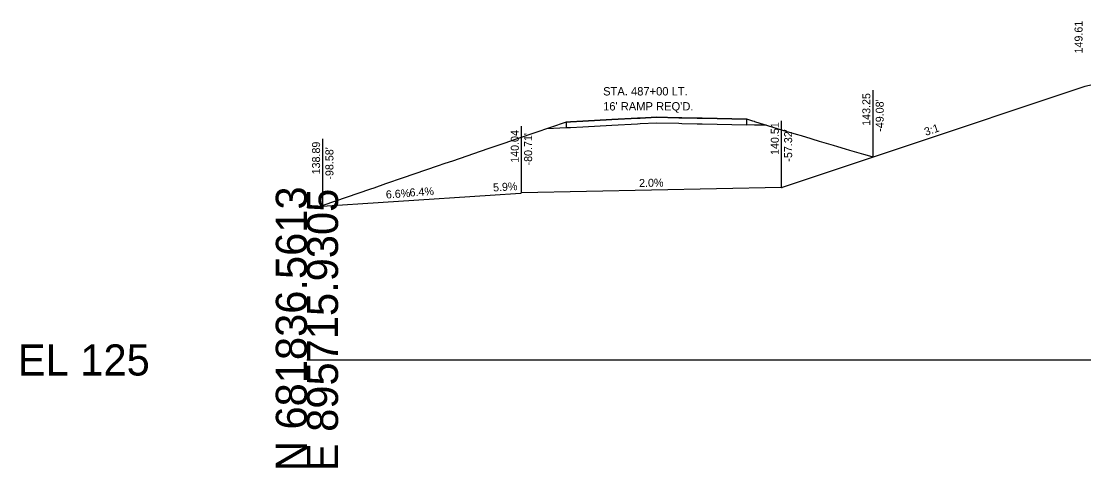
# Model space of a CAD drawing. Extents: x -26 to 4403, y -13 to 9578.
# Drawn here: x 2974.3 to 3069.9, y 8990.3 to 9030.5 of the extents above; entities that cross this region are included whole.
import ezdxf

# ---------------------------------------------------------------- set-up
doc = ezdxf.new("R2010")
doc.units = 0
for name, color, linetype in [('CONST_LV3', 7, 'Continuous'), ('Draft_XS_Grid', 7, 'Continuous'), ('DTM_CONTOURS_MINOR', 7, 'Continuous'), ('DTM_P_FINISHED_GRADE', 7, 'Continuous'), ('DTM_X_GROUND', 7, 'Continuous'), ('X_PROFILES_1', 7, 'Continuous'), ('XS_CELL', 7, 'Continuous'), ('XS_P_DR_GRAVEL', 7, 'Continuous'), ('XS_P_DRAINAGE', 7, 'Continuous'), ('XS_P_GROUND', 7, 'Continuous'), ('XS_P_TX_CLEARZONE', 7, 'Continuous'), ('XS_P_TX_FS_BS', 7, 'Continuous')]:
    doc.layers.add(name, color=color, linetype=linetype)

msp = doc.modelspace()

# ---------------------------------------------------------------- linework, layer by layer
at = {"layer": 'CONST_LV3'}
msp.add_lwpolyline([(3023.32, 9021.398), (3023.721, 9021.419), (3024.83, 9021.479), (3027.436, 9021.619), (3029.722, 9021.741), (3029.968, 9021.754), (3031.434, 9021.833), (3033.452, 9021.782), (3033.707, 9021.776), (3035.107, 9021.741), (3035.54, 9021.732), (3039.561, 9021.644)], dxfattribs=at)
at = {"layer": 'DTM_P_FINISHED_GRADE'}
msp.add_lwpolyline([(3023.32, 9021.398), (3023.721, 9021.419), (3024.83, 9021.479), (3027.436, 9021.619), (3029.722, 9021.741), (3029.968, 9021.754), (3031.434, 9021.833), (3033.452, 9021.782), (3033.707, 9021.776), (3035.106, 9021.741), (3035.539, 9021.732), (3039.561, 9021.644)], dxfattribs=at)
at = {"layer": 'DTM_X_GROUND'}
msp.add_lwpolyline([(3000, 9013.746), (3016.496, 9014.833), (3019.206, 9014.994), (3019.224, 9015.003), (3019.23, 9015.006), (3019.231, 9015.006), (3019.243, 9015.013), (3019.259, 9015.021), (3019.294, 9015.039)], dxfattribs=at)
at = {"layer": 'XS_CELL'}
msp.add_line((3000, 9000), (3100, 9000), dxfattribs=at)
at = {"layer": 'XS_P_DR_GRAVEL'}
for points in [[(3021.592, 9020.805), (3022.17, 9020.836), (3023.32, 9020.898)], [(3023.32, 9021.398), (3023.32, 9020.898), (3023.721, 9020.919), (3024.83, 9020.979), (3027.436, 9021.119), (3029.722, 9021.241), (3029.968, 9021.254), (3031.434, 9021.333), (3033.452, 9021.282), (3033.707, 9021.276), (3035.106, 9021.241), (3035.539, 9021.232), (3039.561, 9021.144), (3039.561, 9021.644), (3035.539, 9021.732), (3035.106, 9021.741), (3033.707, 9021.776), (3033.452, 9021.782), (3031.434, 9021.833), (3029.968, 9021.754), (3029.722, 9021.741), (3027.436, 9021.619), (3024.83, 9021.479), (3023.721, 9021.419), (3023.32, 9021.398)], [(3041.299, 9021.111), (3040.282, 9021.13), (3040.263, 9021.131), (3040.249, 9021.131), (3039.561, 9021.144)]]:
    msp.add_lwpolyline(points, dxfattribs=at)
at = {"layer": 'XS_P_GROUND'}
for points in [[(3042.68, 9015.507), (3053.113, 9018.984), (3070, 9024.612), (3077.434, 9026.389), (3082, 9027.461)], [(3023.32, 9021.398), (3019.082, 9019.945), (3018.81, 9019.852), (3017.719, 9019.478), (3016.259, 9018.977), (3013.082, 9017.888), (3012.417, 9017.66), (3011.718, 9017.42), (3008.645, 9016.367), (3007.08, 9015.83), (3006.012, 9015.464), (3005.717, 9015.363), (3001.424, 9013.891)], [(3050.915, 9018.251), (3050.211, 9018.453), (3050.099, 9018.486), (3048.833, 9018.851), (3048.443, 9018.968), (3047.741, 9019.172), (3047.374, 9019.282), (3046.098, 9019.656), (3044.785, 9020.054), (3044.667, 9020.089), (3044.477, 9020.146), (3044.361, 9020.181), (3044.153, 9020.244), (3043.194, 9020.529), (3040.282, 9021.422), (3040.281, 9021.423), (3040.249, 9021.432), (3040.094, 9021.479), (3039.561, 9021.644)], [(3042.68, 9015.507), (3019.294, 9015.039)]]:
    msp.add_lwpolyline(points, dxfattribs=at)
at = {"layer": 'XS_P_TX_CLEARZONE'}
for p, q in [((3050.915, 9018.251), (3050.915, 9024.251)), ((3019.294, 9015.039), (3019.294, 9021.039)), ((3042.68, 9015.507), (3042.68, 9021.507)), ((3001.424, 9013.891), (3001.424, 9019.891))]:
    msp.add_line(p, q, dxfattribs=at)

# ---------------------------------------------------------------- texts
at = {"layer": 'Draft_XS_Grid'}
msp.add_text('-', height=0.0001, dxfattribs=at).set_placement((3000, 9000))
at = {"layer": 'DTM_CONTOURS_MINOR'}
msp.add_text('X', height=0.12, dxfattribs=at).set_placement((3019.255, 9014.979))
at = {"layer": 'X_PROFILES_1'}
for p in [(3050.876, 9018.191), (3042.641, 9015.447), (3001.385, 9013.831)]:
    msp.add_text('X', height=0.12, dxfattribs=at).set_placement(p)
at = {"layer": 'XS_CELL'}
for s, p in [('N 681836.5613', (3000, 8990)), ('E 895715.9305', (3002.8, 8990))]:
    msp.add_text(s, height=2.8, rotation=90, dxfattribs=at).set_placement(p)
msp.add_text('EL 125', height=2.8, dxfattribs=at).set_placement((2974, 8998.6))
at = {"layer": 'XS_P_DRAINAGE'}
for s, p in [('STA. 487+00 LT.', (3026.639, 9023.788)), ("16' RAMP REQ'D.", (3026.639, 9022.438))]:
    msp.add_text(s, height=0.75, dxfattribs=at).set_placement(p)
at = {"layer": 'XS_P_TX_CLEARZONE'}
for s, p in [('149.61', (3069.76, 9027.564)), ('149.61', (3069.76, 9027.564)), ('143.25', (3050.675, 9021.056)), ("-49.08'", (3051.875, 9020.523)), ('140.51', (3042.44, 9018.436)), ('140.04', (3019.054, 9017.73)), ("-80.71'", (3020.254, 9017.492)), ("-57.32'", (3043.64, 9017.835)), ('138.89', (3001.184, 9016.69)), ("-98.58'", (3002.384, 9016.219))]:
    msp.add_text(s, height=0.72, rotation=90, dxfattribs=at).set_placement(p)
at = {"layer": 'XS_P_TX_FS_BS'}
for s, rotation, p in [('3:1', 18.43323, (3055.665, 9020.151)), ('2.0%', 1.14576, (3029.879, 9015.551)), ('6.6%', 3.76945, (3007.123, 9014.516)), ('6.6%', 3.76945, (3007.123, 9014.516)), ('6.4%', 3.67564, (3009.252, 9014.695)), ('5.9%', 3.40064, (3016.762, 9015.149)), ('5.9%', 3.40064, (3016.762, 9015.149))]:
    msp.add_text(s, height=0.72, rotation=rotation, dxfattribs=at).set_placement(p)

doc.saveas('drawing.dxf')
